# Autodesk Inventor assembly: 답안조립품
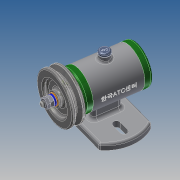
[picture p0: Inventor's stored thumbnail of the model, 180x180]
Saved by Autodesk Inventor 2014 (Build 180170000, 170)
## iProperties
Created: 2017-12
Part Number: 답안조립품
Document SubType Name: Assembly
Designer: kb542-24
Author: kb542-24
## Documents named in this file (14)
- C:\Users\kb542-24\Desktop\471207V1030\답안조립품.iam
- C:\Users\kb542-24\Desktop\471207V1030\1_본체.ipt
- C:\Users\kb542-24\Desktop\471207V1030\축.ipt
- C:\Users\kb542-24\Desktop\471207V1030\베어링 15 x 32 x 9.ipt
- C:\Users\kb542-24\Desktop\471207V1030\키 3 x 3 x 12.ipt
- C:\Users\kb542-24\Desktop\471207V1030\V벨트풀리.ipt
- C:\Users\kb542-24\Desktop\471207V1030\와셔 8x17.ipt
- C:\Users\kb542-24\Desktop\471207V1030\스프링와셔 8.ipt
- C:\Users\kb542-24\Desktop\471207V1030\너트 M 8.ipt
- C:\Users\kb542-24\Desktop\471207V1030\뒤커버.ipt
- C:\Users\kb542-24\Desktop\471207V1030\앞커버.ipt
- C:\Users\kb542-24\Desktop\471207V1030\오일 실 15 25 7.ipt
- C:\Users\kb542-24\Desktop\471207V1030\볼트 M4 x 12.ipt
- C:\Users\kb542-24\Desktop\471207V1030\고무캡.ipt
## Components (3 placed, 3 different names)
1. 1_본체:1
2. V벨트풀리:1
3. 고무캡:1
